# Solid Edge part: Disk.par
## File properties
Author: CADCIM
Template: NORMENG.PAR
Last saved by: CADCIM
Revision: 5
Application: Solid Edge
Density: 0 lbm/in^3
Accuracy: 0.99
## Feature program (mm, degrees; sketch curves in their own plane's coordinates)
sketch for "unnamed Protrusion 1" plane through (0, 0, 0) normal (0, 0, 1) x-axis (1, 0, 0)
  line (-3.175, 25.2008) -> (-3.175, 20.6375)
  arc centre (0, 20.6375) radius 3.175 from (-3.175, 20.6375) to (3.175, 20.6375) ccw
  line (3.175, 20.6375) -> (3.175, 25.2008)
  arc centre (0, 0) radius 25.4 from (3.175, 25.2008) to (25.2008, 3.175) cw
  line (25.2008, 3.175) -> (20.6375, 3.175)
  arc centre (20.6375, 0) radius 3.175 from (20.6375, 3.175) to (20.6375, -3.175) ccw
  line (20.6375, -3.175) -> (25.2008, -3.175)
  arc centre (0, 0) radius 25.4 from (25.2008, -3.175) to (3.1784, -25.2004) cw
  line (3.1784, -20.6375) -> (3.1784, -25.2004)
  arc centre (0, -20.6375) radius 3.1784 from (-3.1784, -20.6375) to (3.1784, -20.6375) cw
  line (-3.1784, -25.2004) -> (-3.1784, -20.6375)
  arc centre (0, 0) radius 25.4 from (-3.1784, -25.2004) to (-25.2008, -3.175) cw
  line (-20.6375, -3.175) -> (-25.2008, -3.175)
  arc centre (-20.6375, 0) radius 3.175 from (-20.6375, 3.175) to (-20.6375, -3.175) cw
  line (-25.2008, 3.175) -> (-20.6375, 3.175)
extrude "unnamed Protrusion 1" add finite 3.175 along +normal
sketch for "Hole_1" plane through (0, 0, 3.175) normal (0, 0, 1) x-axis (1, 0, 0)
  hole centre (0, 0) bore radius 12.7
hole "Hole_1" diameter 25.4 through
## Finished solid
Body 1: solid body, 19 faces, 50 edges, 32 vertices.
  Faces by surface: plane 10, cylinder 9
  Edges by curve: line 32, circle 18
Bounding box of the edges (mm): 50.402 x 50.401 x 3.175, from (-25.2008, -25.2004, 0) to (25.2008, 25.2008, 3.175).
Cylindrical faces by radius (mm): R3.175 x3, R3.1784 x1, R12.7 x1, R25.4 x4
Planar faces by outward normal: +x 2, +y 2, +z 1, -x 2, -y 2, -z 1
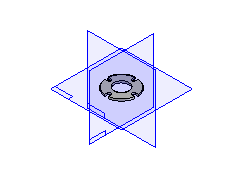
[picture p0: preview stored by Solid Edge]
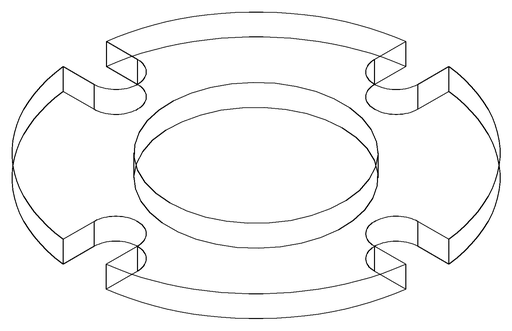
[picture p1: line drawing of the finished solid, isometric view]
